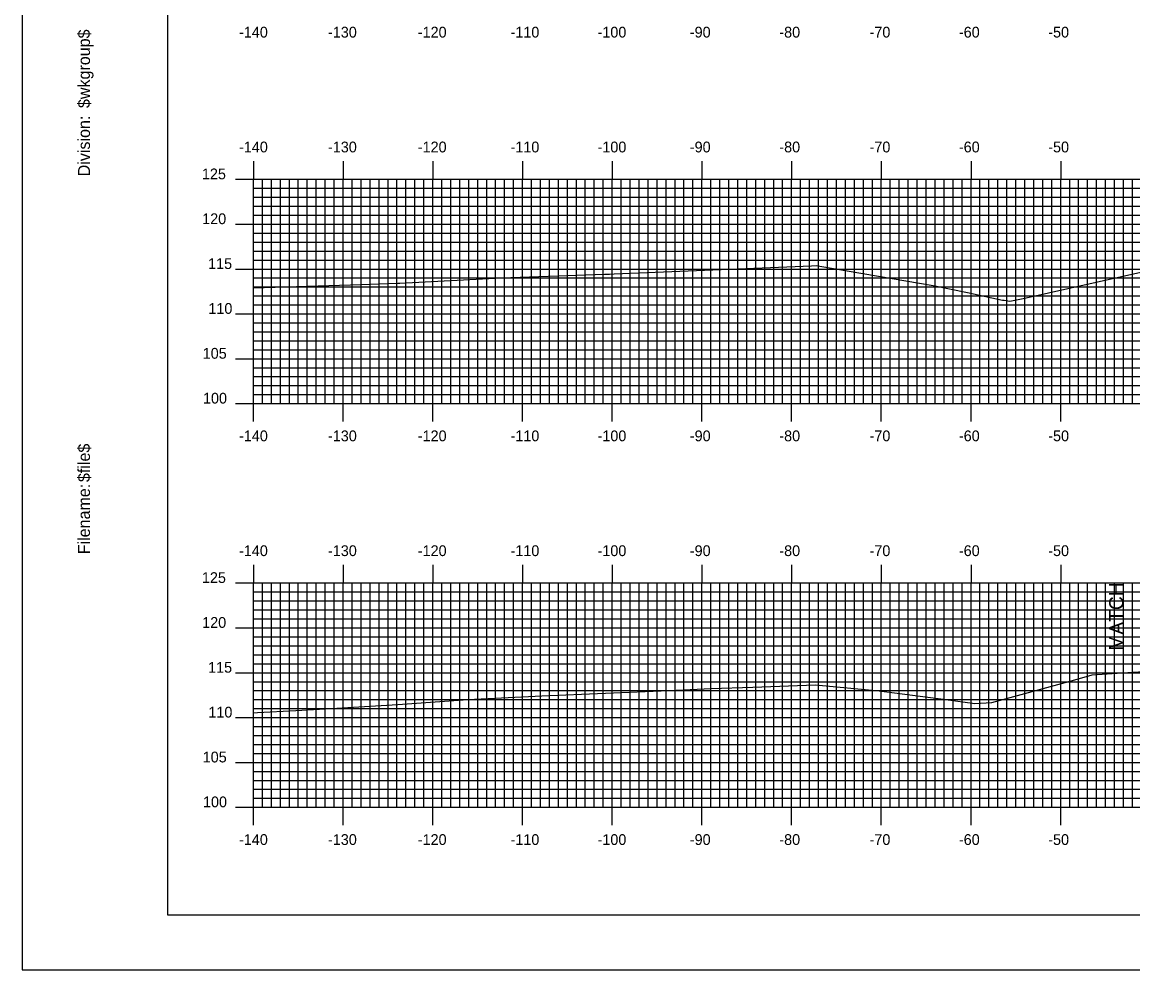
# Model space of a CAD drawing. Extents: x 1685586 to 1685929, y 461260 to 461480.
# Drawn here: x 1685586 to 1685709.8, y 461260 to 461365.6 of the extents above; entities that cross this region are included whole.
import ezdxf

# ---------------------------------------------------------------- set-up
doc = ezdxf.new("R2010")
doc.units = 0
for name, color, linetype in [('ANNOTATION', 7, 'Continuous'), ('BORDER', 7, 'Continuous'), ('H_V ANNOTATION', 7, 'Continuous'), ('MAJOR', 7, 'Continuous'), ('MINOR', 7, 'Continuous'), ('PLOT BOUNDARY', 7, 'Continuous'), ('S_Roadway_Centerline', 7, 'Continuous')]:
    doc.layers.add(name, color=color, linetype=linetype)

msp = doc.modelspace()

# ---------------------------------------------------------------- linework, layer by layer
at = {"layer": 'BORDER'}
msp.add_lwpolyline([(1685602.14, 461266.07), (1685922.14, 461266.07), (1685922.14, 461476.07), (1685602.14, 461476.07)], close=True, dxfattribs=at)
at = {"layer": 'MAJOR'}
for p, q in [((1685611.74, 461350.08), (1685611.74, 461348.07)), ((1685621.74, 461350.08), (1685621.74, 461348.07)), ((1685631.74, 461350.08), (1685631.74, 461348.07)), ((1685641.74, 461350.08), (1685641.74, 461348.07)), ((1685651.74, 461350.08), (1685651.74, 461348.07)), ((1685661.74, 461350.08), (1685661.74, 461348.07)), ((1685671.74, 461350.08), (1685671.74, 461348.07)), ((1685681.74, 461350.08), (1685681.74, 461348.07)), ((1685691.74, 461350.08), (1685691.74, 461348.07)), ((1685701.74, 461350.08), (1685701.74, 461348.07)), ((1685609.74, 461348.07), (1685611.74, 461348.07)), ((1685611.74, 461348.07), (1685891.74, 461348.07)), ((1685611.74, 461323.07), (1685611.74, 461348.07)), ((1685611.74, 461323.07), (1685611.74, 461348.07)), ((1685611.74, 461348.07), (1685891.74, 461348.07)), ((1685621.74, 461323.07), (1685621.74, 461348.07)), ((1685631.74, 461323.07), (1685631.74, 461348.07)), ((1685641.74, 461323.07), (1685641.74, 461348.07)), ((1685651.74, 461323.07), (1685651.74, 461348.07)), ((1685661.74, 461323.07), (1685661.74, 461348.07)), ((1685671.74, 461323.07), (1685671.74, 461348.07)), ((1685681.74, 461323.07), (1685681.74, 461348.07)), ((1685691.74, 461323.07), (1685691.74, 461348.07)), ((1685701.74, 461323.07), (1685701.74, 461348.07)), ((1685609.74, 461343.07), (1685611.74, 461343.07)), ((1685611.74, 461343.07), (1685891.74, 461343.07)), ((1685609.74, 461338.07), (1685611.74, 461338.07)), ((1685611.74, 461338.07), (1685891.74, 461338.07)), ((1685609.74, 461333.07), (1685611.74, 461333.07)), ((1685611.74, 461333.07), (1685891.74, 461333.07)), ((1685609.74, 461328.07), (1685611.74, 461328.07)), ((1685611.74, 461328.07), (1685891.74, 461328.07)), ((1685609.74, 461323.07), (1685611.74, 461323.07)), ((1685611.74, 461323.07), (1685891.74, 461323.07)), ((1685611.74, 461323.07), (1685891.74, 461323.07)), ((1685611.74, 461321.07), (1685611.74, 461323.07)), ((1685621.74, 461321.07), (1685621.74, 461323.07)), ((1685631.74, 461321.07), (1685631.74, 461323.07)), ((1685641.74, 461321.07), (1685641.74, 461323.07)), ((1685651.74, 461321.07), (1685651.74, 461323.07)), ((1685661.74, 461321.07), (1685661.74, 461323.07)), ((1685671.74, 461321.07), (1685671.74, 461323.07)), ((1685681.74, 461321.07), (1685681.74, 461323.07)), ((1685691.74, 461321.07), (1685691.74, 461323.07)), ((1685701.74, 461321.07), (1685701.74, 461323.07)), ((1685611.74, 461305.08), (1685611.74, 461303.07)), ((1685621.74, 461305.08), (1685621.74, 461303.07)), ((1685631.74, 461305.08), (1685631.74, 461303.07)), ((1685641.74, 461305.08), (1685641.74, 461303.07)), ((1685651.74, 461305.08), (1685651.74, 461303.07)), ((1685661.74, 461305.08), (1685661.74, 461303.07)), ((1685671.74, 461305.08), (1685671.74, 461303.07)), ((1685681.74, 461305.08), (1685681.74, 461303.07)), ((1685691.74, 461305.08), (1685691.74, 461303.07)), ((1685701.74, 461305.08), (1685701.74, 461303.07)), ((1685609.74, 461303.07), (1685611.74, 461303.07)), ((1685611.74, 461303.07), (1685891.74, 461303.07)), ((1685611.74, 461278.07), (1685611.74, 461303.07)), ((1685611.74, 461278.07), (1685611.74, 461303.07)), ((1685611.74, 461303.07), (1685891.74, 461303.07)), ((1685621.74, 461278.07), (1685621.74, 461303.07)), ((1685631.74, 461278.07), (1685631.74, 461303.07)), ((1685641.74, 461278.07), (1685641.74, 461303.07)), ((1685651.74, 461278.07), (1685651.74, 461303.07)), ((1685661.74, 461278.07), (1685661.74, 461303.07)), ((1685671.74, 461278.07), (1685671.74, 461303.07)), ((1685681.74, 461278.07), (1685681.74, 461303.07)), ((1685691.74, 461278.07), (1685691.74, 461303.07)), ((1685701.74, 461278.07), (1685701.74, 461303.07)), ((1685609.74, 461298.07), (1685611.74, 461298.07)), ((1685611.74, 461298.07), (1685891.74, 461298.07)), ((1685609.74, 461293.07), (1685611.74, 461293.07)), ((1685611.74, 461293.07), (1685891.74, 461293.07)), ((1685609.74, 461288.07), (1685611.74, 461288.07)), ((1685611.74, 461288.07), (1685891.74, 461288.07)), ((1685609.74, 461283.07), (1685611.74, 461283.07)), ((1685611.74, 461283.07), (1685891.74, 461283.07)), ((1685609.74, 461278.07), (1685611.74, 461278.07)), ((1685611.74, 461278.07), (1685891.74, 461278.07)), ((1685611.74, 461278.07), (1685891.74, 461278.07)), ((1685611.74, 461276.07), (1685611.74, 461278.07)), ((1685621.74, 461276.07), (1685621.74, 461278.07)), ((1685631.74, 461276.07), (1685631.74, 461278.07)), ((1685641.74, 461276.07), (1685641.74, 461278.07)), ((1685651.74, 461276.07), (1685651.74, 461278.07)), ((1685661.74, 461276.07), (1685661.74, 461278.07)), ((1685671.74, 461276.07), (1685671.74, 461278.07)), ((1685681.74, 461276.07), (1685681.74, 461278.07)), ((1685691.74, 461276.07), (1685691.74, 461278.07)), ((1685701.74, 461276.07), (1685701.74, 461278.07))]:
    msp.add_line(p, q, dxfattribs=at)
at = {"layer": 'MINOR'}
for p, q in [((1685612.74, 461323.07), (1685612.74, 461348.07)), ((1685613.74, 461323.07), (1685613.74, 461348.07)), ((1685614.74, 461323.07), (1685614.74, 461348.07)), ((1685615.74, 461323.07), (1685615.74, 461348.07)), ((1685616.74, 461323.07), (1685616.74, 461348.07)), ((1685617.74, 461323.07), (1685617.74, 461348.07)), ((1685618.74, 461323.07), (1685618.74, 461348.07)), ((1685619.74, 461323.07), (1685619.74, 461348.07)), ((1685620.74, 461323.07), (1685620.74, 461348.07)), ((1685622.74, 461323.07), (1685622.74, 461348.07)), ((1685623.74, 461323.07), (1685623.74, 461348.07)), ((1685624.74, 461323.07), (1685624.74, 461348.07)), ((1685625.74, 461323.07), (1685625.74, 461348.07)), ((1685626.74, 461323.07), (1685626.74, 461348.07)), ((1685627.74, 461323.07), (1685627.74, 461348.07)), ((1685628.74, 461323.07), (1685628.74, 461348.07)), ((1685629.74, 461323.07), (1685629.74, 461348.07)), ((1685630.74, 461323.07), (1685630.74, 461348.07)), ((1685632.74, 461323.07), (1685632.74, 461348.07)), ((1685633.74, 461323.07), (1685633.74, 461348.07)), ((1685634.74, 461323.07), (1685634.74, 461348.07)), ((1685635.74, 461323.07), (1685635.74, 461348.07)), ((1685636.74, 461323.07), (1685636.74, 461348.07)), ((1685637.74, 461323.07), (1685637.74, 461348.07)), ((1685638.74, 461323.07), (1685638.74, 461348.07)), ((1685639.74, 461323.07), (1685639.74, 461348.07)), ((1685640.74, 461323.07), (1685640.74, 461348.07)), ((1685642.74, 461323.07), (1685642.74, 461348.07)), ((1685643.74, 461323.07), (1685643.74, 461348.07)), ((1685644.74, 461323.07), (1685644.74, 461348.07)), ((1685645.74, 461323.07), (1685645.74, 461348.07)), ((1685646.74, 461323.07), (1685646.74, 461348.07)), ((1685647.74, 461323.07), (1685647.74, 461348.07)), ((1685648.74, 461323.07), (1685648.74, 461348.07)), ((1685649.74, 461323.07), (1685649.74, 461348.07)), ((1685650.74, 461323.07), (1685650.74, 461348.07)), ((1685652.74, 461323.07), (1685652.74, 461348.07)), ((1685653.74, 461323.07), (1685653.74, 461348.07)), ((1685654.74, 461323.07), (1685654.74, 461348.07)), ((1685655.74, 461323.07), (1685655.74, 461348.07)), ((1685656.74, 461323.07), (1685656.74, 461348.07)), ((1685657.74, 461323.07), (1685657.74, 461348.07)), ((1685658.74, 461323.07), (1685658.74, 461348.07)), ((1685659.74, 461323.07), (1685659.74, 461348.07)), ((1685660.74, 461323.07), (1685660.74, 461348.07)), ((1685662.74, 461323.07), (1685662.74, 461348.07)), ((1685663.74, 461323.07), (1685663.74, 461348.07)), ((1685664.74, 461323.07), (1685664.74, 461348.07)), ((1685665.74, 461323.07), (1685665.74, 461348.07)), ((1685666.74, 461323.07), (1685666.74, 461348.07)), ((1685667.74, 461323.07), (1685667.74, 461348.07)), ((1685668.74, 461323.07), (1685668.74, 461348.07)), ((1685669.74, 461323.07), (1685669.74, 461348.07)), ((1685670.74, 461323.07), (1685670.74, 461348.07)), ((1685672.74, 461323.07), (1685672.74, 461348.07)), ((1685673.74, 461323.07), (1685673.74, 461348.07)), ((1685674.74, 461323.07), (1685674.74, 461348.07)), ((1685675.74, 461323.07), (1685675.74, 461348.07)), ((1685676.74, 461323.07), (1685676.74, 461348.07)), ((1685677.74, 461323.07), (1685677.74, 461348.07)), ((1685678.74, 461323.07), (1685678.74, 461348.07)), ((1685679.74, 461323.07), (1685679.74, 461348.07)), ((1685680.74, 461323.07), (1685680.74, 461348.07)), ((1685682.74, 461323.07), (1685682.74, 461348.07)), ((1685683.74, 461323.07), (1685683.74, 461348.07)), ((1685684.74, 461323.07), (1685684.74, 461348.07)), ((1685685.74, 461323.07), (1685685.74, 461348.07)), ((1685686.74, 461323.07), (1685686.74, 461348.07)), ((1685687.74, 461323.07), (1685687.74, 461348.07)), ((1685688.74, 461323.07), (1685688.74, 461348.07)), ((1685689.74, 461323.07), (1685689.74, 461348.07)), ((1685690.74, 461323.07), (1685690.74, 461348.07)), ((1685692.74, 461323.07), (1685692.74, 461348.07)), ((1685693.74, 461323.07), (1685693.74, 461348.07)), ((1685694.74, 461323.07), (1685694.74, 461348.07)), ((1685695.74, 461323.07), (1685695.74, 461348.07)), ((1685696.74, 461323.07), (1685696.74, 461348.07)), ((1685697.74, 461323.07), (1685697.74, 461348.07)), ((1685698.74, 461323.07), (1685698.74, 461348.07)), ((1685699.74, 461323.07), (1685699.74, 461348.07)), ((1685700.74, 461323.07), (1685700.74, 461348.07)), ((1685702.74, 461323.07), (1685702.74, 461348.07)), ((1685703.74, 461323.07), (1685703.74, 461348.07)), ((1685704.74, 461323.07), (1685704.74, 461348.07)), ((1685705.74, 461323.07), (1685705.74, 461348.07)), ((1685706.74, 461323.07), (1685706.74, 461348.07)), ((1685707.74, 461323.07), (1685707.74, 461348.07)), ((1685708.74, 461323.07), (1685708.74, 461348.07)), ((1685709.74, 461323.07), (1685709.74, 461348.07)), ((1685611.74, 461347.07), (1685891.74, 461347.07)), ((1685611.74, 461347.07), (1685613.75, 461347.07)), ((1685611.74, 461346.07), (1685891.74, 461346.07)), ((1685611.74, 461346.07), (1685613.75, 461346.07)), ((1685611.74, 461345.07), (1685891.74, 461345.07)), ((1685611.74, 461345.07), (1685613.75, 461345.07)), ((1685611.74, 461344.07), (1685891.74, 461344.07)), ((1685611.74, 461344.07), (1685613.75, 461344.07)), ((1685611.74, 461342.07), (1685891.74, 461342.07)), ((1685611.74, 461342.07), (1685613.75, 461342.07)), ((1685611.74, 461341.07), (1685891.74, 461341.07)), ((1685611.74, 461341.07), (1685613.75, 461341.07)), ((1685611.74, 461340.07), (1685891.74, 461340.07)), ((1685611.74, 461340.07), (1685613.75, 461340.07)), ((1685611.74, 461339.07), (1685891.74, 461339.07)), ((1685611.74, 461339.07), (1685613.75, 461339.07)), ((1685611.74, 461337.07), (1685891.74, 461337.07)), ((1685611.74, 461337.07), (1685613.75, 461337.07)), ((1685611.74, 461336.07), (1685891.74, 461336.07)), ((1685611.74, 461336.07), (1685613.75, 461336.07)), ((1685611.74, 461335.07), (1685891.74, 461335.07)), ((1685611.74, 461335.07), (1685613.75, 461335.07)), ((1685611.74, 461334.07), (1685891.74, 461334.07)), ((1685611.74, 461334.07), (1685613.75, 461334.07)), ((1685611.74, 461332.07), (1685891.74, 461332.07)), ((1685611.74, 461332.07), (1685613.75, 461332.07)), ((1685611.74, 461331.07), (1685891.74, 461331.07)), ((1685611.74, 461331.07), (1685613.75, 461331.07)), ((1685611.74, 461330.07), (1685891.74, 461330.07)), ((1685611.74, 461330.07), (1685613.75, 461330.07)), ((1685611.74, 461329.07), (1685891.74, 461329.07)), ((1685611.74, 461329.07), (1685613.75, 461329.07)), ((1685611.74, 461327.07), (1685891.74, 461327.07)), ((1685611.74, 461327.07), (1685613.75, 461327.07)), ((1685611.74, 461326.07), (1685891.74, 461326.07)), ((1685611.74, 461326.07), (1685613.75, 461326.07)), ((1685611.74, 461325.07), (1685891.74, 461325.07)), ((1685611.74, 461325.07), (1685613.75, 461325.07)), ((1685611.74, 461324.07), (1685891.74, 461324.07)), ((1685611.74, 461324.07), (1685613.75, 461324.07)), ((1685612.74, 461278.07), (1685612.74, 461303.07)), ((1685613.74, 461278.07), (1685613.74, 461303.07)), ((1685614.74, 461278.07), (1685614.74, 461303.07)), ((1685615.74, 461278.07), (1685615.74, 461303.07)), ((1685616.74, 461278.07), (1685616.74, 461303.07)), ((1685617.74, 461278.07), (1685617.74, 461303.07)), ((1685618.74, 461278.07), (1685618.74, 461303.07)), ((1685619.74, 461278.07), (1685619.74, 461303.07)), ((1685620.74, 461278.07), (1685620.74, 461303.07)), ((1685622.74, 461278.07), (1685622.74, 461303.07)), ((1685623.74, 461278.07), (1685623.74, 461303.07)), ((1685624.74, 461278.07), (1685624.74, 461303.07)), ((1685625.74, 461278.07), (1685625.74, 461303.07)), ((1685626.74, 461278.07), (1685626.74, 461303.07)), ((1685627.74, 461278.07), (1685627.74, 461303.07)), ((1685628.74, 461278.07), (1685628.74, 461303.07)), ((1685629.74, 461278.07), (1685629.74, 461303.07)), ((1685630.74, 461278.07), (1685630.74, 461303.07)), ((1685632.74, 461278.07), (1685632.74, 461303.07)), ((1685633.74, 461278.07), (1685633.74, 461303.07)), ((1685634.74, 461278.07), (1685634.74, 461303.07)), ((1685635.74, 461278.07), (1685635.74, 461303.07)), ((1685636.74, 461278.07), (1685636.74, 461303.07)), ((1685637.74, 461278.07), (1685637.74, 461303.07)), ((1685638.74, 461278.07), (1685638.74, 461303.07)), ((1685639.74, 461278.07), (1685639.74, 461303.07)), ((1685640.74, 461278.07), (1685640.74, 461303.07)), ((1685642.74, 461278.07), (1685642.74, 461303.07)), ((1685643.74, 461278.07), (1685643.74, 461303.07)), ((1685644.74, 461278.07), (1685644.74, 461303.07)), ((1685645.74, 461278.07), (1685645.74, 461303.07)), ((1685646.74, 461278.07), (1685646.74, 461303.07)), ((1685647.74, 461278.07), (1685647.74, 461303.07)), ((1685648.74, 461278.07), (1685648.74, 461303.07)), ((1685649.74, 461278.07), (1685649.74, 461303.07)), ((1685650.74, 461278.07), (1685650.74, 461303.07)), ((1685652.74, 461278.07), (1685652.74, 461303.07)), ((1685653.74, 461278.07), (1685653.74, 461303.07)), ((1685654.74, 461278.07), (1685654.74, 461303.07)), ((1685655.74, 461278.07), (1685655.74, 461303.07)), ((1685656.74, 461278.07), (1685656.74, 461303.07)), ((1685657.74, 461278.07), (1685657.74, 461303.07)), ((1685658.74, 461278.07), (1685658.74, 461303.07)), ((1685659.74, 461278.07), (1685659.74, 461303.07)), ((1685660.74, 461278.07), (1685660.74, 461303.07)), ((1685662.74, 461278.07), (1685662.74, 461303.07)), ((1685663.74, 461278.07), (1685663.74, 461303.07)), ((1685664.74, 461278.07), (1685664.74, 461303.07)), ((1685665.74, 461278.07), (1685665.74, 461303.07)), ((1685666.74, 461278.07), (1685666.74, 461303.07)), ((1685667.74, 461278.07), (1685667.74, 461303.07)), ((1685668.74, 461278.07), (1685668.74, 461303.07)), ((1685669.74, 461278.07), (1685669.74, 461303.07)), ((1685670.74, 461278.07), (1685670.74, 461303.07)), ((1685672.74, 461278.07), (1685672.74, 461303.07)), ((1685673.74, 461278.07), (1685673.74, 461303.07)), ((1685674.74, 461278.07), (1685674.74, 461303.07)), ((1685675.74, 461278.07), (1685675.74, 461303.07)), ((1685676.74, 461278.07), (1685676.74, 461303.07)), ((1685677.74, 461278.07), (1685677.74, 461303.07)), ((1685678.74, 461278.07), (1685678.74, 461303.07)), ((1685679.74, 461278.07), (1685679.74, 461303.07)), ((1685680.74, 461278.07), (1685680.74, 461303.07)), ((1685682.74, 461278.07), (1685682.74, 461303.07)), ((1685683.74, 461278.07), (1685683.74, 461303.07)), ((1685684.74, 461278.07), (1685684.74, 461303.07)), ((1685685.74, 461278.07), (1685685.74, 461303.07)), ((1685686.74, 461278.07), (1685686.74, 461303.07)), ((1685687.74, 461278.07), (1685687.74, 461303.07)), ((1685688.74, 461278.07), (1685688.74, 461303.07)), ((1685689.74, 461278.07), (1685689.74, 461303.07)), ((1685690.74, 461278.07), (1685690.74, 461303.07)), ((1685692.74, 461278.07), (1685692.74, 461303.07)), ((1685693.74, 461278.07), (1685693.74, 461303.07)), ((1685694.74, 461278.07), (1685694.74, 461303.07)), ((1685695.74, 461278.07), (1685695.74, 461303.07)), ((1685696.74, 461278.07), (1685696.74, 461303.07)), ((1685697.74, 461278.07), (1685697.74, 461303.07)), ((1685698.74, 461278.07), (1685698.74, 461303.07)), ((1685699.74, 461278.07), (1685699.74, 461303.07)), ((1685700.74, 461278.07), (1685700.74, 461303.07)), ((1685702.74, 461278.07), (1685702.74, 461303.07)), ((1685703.74, 461278.07), (1685703.74, 461303.07)), ((1685704.74, 461278.07), (1685704.74, 461303.07)), ((1685705.74, 461278.07), (1685705.74, 461303.07)), ((1685706.74, 461278.07), (1685706.74, 461303.07)), ((1685707.74, 461278.07), (1685707.74, 461303.07)), ((1685708.74, 461278.07), (1685708.74, 461303.07)), ((1685709.74, 461278.07), (1685709.74, 461303.07)), ((1685611.74, 461302.07), (1685891.74, 461302.07)), ((1685611.74, 461302.07), (1685613.75, 461302.07)), ((1685611.74, 461301.07), (1685891.74, 461301.07)), ((1685611.74, 461301.07), (1685613.75, 461301.07)), ((1685611.74, 461300.07), (1685891.74, 461300.07)), ((1685611.74, 461300.07), (1685613.75, 461300.07)), ((1685611.74, 461299.07), (1685891.74, 461299.07)), ((1685611.74, 461299.07), (1685613.75, 461299.07)), ((1685611.74, 461297.07), (1685891.74, 461297.07)), ((1685611.74, 461297.07), (1685613.75, 461297.07)), ((1685611.74, 461296.07), (1685891.74, 461296.07)), ((1685611.74, 461296.07), (1685613.75, 461296.07)), ((1685611.74, 461295.07), (1685891.74, 461295.07)), ((1685611.74, 461295.07), (1685613.75, 461295.07)), ((1685611.74, 461294.07), (1685891.74, 461294.07)), ((1685611.74, 461294.07), (1685613.75, 461294.07)), ((1685611.74, 461292.07), (1685891.74, 461292.07)), ((1685611.74, 461292.07), (1685613.75, 461292.07)), ((1685611.74, 461291.07), (1685891.74, 461291.07)), ((1685611.74, 461291.07), (1685613.75, 461291.07)), ((1685611.74, 461290.07), (1685891.74, 461290.07)), ((1685611.74, 461290.07), (1685613.75, 461290.07)), ((1685611.74, 461289.07), (1685891.74, 461289.07)), ((1685611.74, 461289.07), (1685613.75, 461289.07)), ((1685611.74, 461287.07), (1685891.74, 461287.07)), ((1685611.74, 461287.07), (1685613.75, 461287.07)), ((1685611.74, 461286.07), (1685891.74, 461286.07)), ((1685611.74, 461286.07), (1685613.75, 461286.07)), ((1685611.74, 461285.07), (1685891.74, 461285.07)), ((1685611.74, 461285.07), (1685613.75, 461285.07)), ((1685611.74, 461284.07), (1685891.74, 461284.07)), ((1685611.74, 461284.07), (1685613.75, 461284.07)), ((1685611.74, 461282.07), (1685891.74, 461282.07)), ((1685611.74, 461282.07), (1685613.75, 461282.07)), ((1685611.74, 461281.07), (1685891.74, 461281.07)), ((1685611.74, 461281.07), (1685613.75, 461281.07)), ((1685611.74, 461280.07), (1685891.74, 461280.07)), ((1685611.74, 461280.07), (1685613.75, 461280.07)), ((1685611.74, 461279.07), (1685891.74, 461279.07)), ((1685611.74, 461279.07), (1685613.75, 461279.07))]:
    msp.add_line(p, q, dxfattribs=at)
at = {"layer": 'PLOT BOUNDARY'}
msp.add_lwpolyline([(1685585.96, 461259.95), (1685925.96, 461259.95), (1685925.96, 461479.95), (1685585.96, 461479.95)], close=True, dxfattribs=at)
at = {"layer": 'S_Roadway_Centerline'}
for points in [[(1685611.74, 461335.98), (1685623.74, 461336.35), (1685627.82, 461336.49), (1685628.07, 461336.5), (1685639.39, 461337.08), (1685650.89, 461337.49), (1685651.43, 461337.51), (1685651.96, 461337.52), (1685673.97, 461338.44), (1685674.49, 461338.46), (1685675.1, 461338.36), (1685687.51, 461336.24), (1685691.36, 461335.44), (1685695.25, 461334.6), (1685695.42, 461334.58), (1685696.07, 461334.47), (1685697.54, 461334.78), (1685713.82, 461338.42)], [(1685611.74, 461288.61), (1685612.18, 461288.63), (1685616.45, 461288.87), (1685620.42, 461289.08), (1685627.84, 461289.51), (1685635.64, 461290.09), (1685643.88, 461290.49), (1685658.08, 461291.09), (1685662.78, 461291.3), (1685667.43, 461291.47), (1685674.42, 461291.71), (1685681.5, 461291.05), (1685688.94, 461290.1), (1685692.16, 461289.65), (1685694.06, 461289.74), (1685703.06, 461292.21), (1685705.26, 461292.83), (1685708.03, 461293.01), (1685714.61, 461293.42)]]:
    msp.add_lwpolyline(points, dxfattribs=at)

# ---------------------------------------------------------------- texts
at = {"layer": 'ANNOTATION'}
msp.add_text('MATCH', height=1.6, rotation=90, dxfattribs=at).set_placement((1685708.74, 461295.53))
at = {"layer": 'BORDER'}
for s, p in [('$wkgroup$', (1685593.51, 461356.01)), ('Division:', (1685593.51, 461348.4)), ('$file$', (1685593.51, 461314.32)), ('Filename:', (1685593.51, 461306.27))]:
    msp.add_text(s, height=1.339, rotation=90, dxfattribs=at).set_placement(p)
at = {"layer": 'H_V ANNOTATION'}
for s, p in [('-140', (1685610.13, 461363.87)), ('-130', (1685620.05, 461363.87)), ('-120', (1685630.06, 461363.87)), ('-110', (1685640.4, 461363.87)), ('-100', (1685650.1, 461363.87)), ('-90', (1685660.39, 461363.87)), ('-80', (1685670.37, 461363.87)), ('-70', (1685680.43, 461363.87)), ('-60', (1685690.39, 461363.87)), ('-50', (1685700.35, 461363.87)), ('-140', (1685610.13, 461351.07)), ('-130', (1685620.05, 461351.07)), ('-120', (1685630.06, 461351.07)), ('-110', (1685640.4, 461351.07)), ('-100', (1685650.1, 461351.07)), ('-90', (1685660.39, 461351.07)), ('-80', (1685670.37, 461351.07)), ('-70', (1685680.43, 461351.07)), ('-60', (1685690.39, 461351.07)), ('-50', (1685700.35, 461351.07)), ('125', (1685605.99, 461348.07)), ('120', (1685606.02, 461343.07)), ('115', (1685606.68, 461338.07)), ('110', (1685606.71, 461333.07)), ('105', (1685606.08, 461328.07)), ('100', (1685606.11, 461323.07)), ('-140', (1685610.13, 461318.87)), ('-130', (1685620.05, 461318.87)), ('-120', (1685630.06, 461318.87)), ('-110', (1685640.4, 461318.87)), ('-100', (1685650.1, 461318.87)), ('-90', (1685660.39, 461318.87)), ('-80', (1685670.37, 461318.87)), ('-70', (1685680.43, 461318.87)), ('-60', (1685690.39, 461318.87)), ('-50', (1685700.35, 461318.87)), ('-140', (1685610.13, 461306.07)), ('-130', (1685620.05, 461306.07)), ('-120', (1685630.06, 461306.07)), ('-110', (1685640.4, 461306.07)), ('-100', (1685650.1, 461306.07)), ('-90', (1685660.39, 461306.07)), ('-80', (1685670.37, 461306.07)), ('-70', (1685680.43, 461306.07)), ('-60', (1685690.39, 461306.07)), ('-50', (1685700.35, 461306.07)), ('125', (1685605.99, 461303.07)), ('120', (1685606.02, 461298.07)), ('115', (1685606.68, 461293.07)), ('110', (1685606.71, 461288.07)), ('105', (1685606.08, 461283.07)), ('100', (1685606.11, 461278.07)), ('-140', (1685610.13, 461273.87)), ('-130', (1685620.05, 461273.87)), ('-120', (1685630.06, 461273.87)), ('-110', (1685640.4, 461273.87)), ('-100', (1685650.1, 461273.87)), ('-90', (1685660.39, 461273.87)), ('-80', (1685670.37, 461273.87)), ('-70', (1685680.43, 461273.87)), ('-60', (1685690.39, 461273.87)), ('-50', (1685700.35, 461273.87))]:
    msp.add_text(s, height=1.2, dxfattribs=at).set_placement(p)
at = {"layer": 'MAJOR'}
for p in [(1685611.73, 461323.07), (1685611.73, 461278.07)]:
    msp.add_text('-', height=0.012, dxfattribs=at).set_placement(p)

doc.saveas('drawing.dxf')
